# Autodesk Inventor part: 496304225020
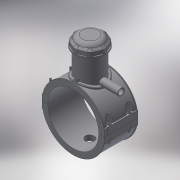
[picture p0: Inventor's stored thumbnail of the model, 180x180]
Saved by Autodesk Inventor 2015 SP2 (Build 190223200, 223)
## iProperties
Created: 2017-07
Part Number: 496304225020
Material: Generic
Description: PLASSON TAPPING SADDLE 225x20
Document SubType Name: Modeling
Designer: KIM
Mass: 1584.4 g
Surface Area: 3366.97 cm^2
Volume: 1584.4 cm^3
Density: 1 g/cm^3
Appearance: Default
Author: KIM
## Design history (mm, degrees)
derived "496304.ipt"
feature "Solid1::496304.ipt"
feature "Solid2::496304.ipt"
feature "Solid4::496304.ipt"
feature "Solid5::496304.ipt"
tag "TaggingFeature1" dims "B_" = 227
body "Solid1"
body "Solid2"
other parameters: "d_" = 225, "L_" = 176, "d_t" = 6, "H_2" = 177, "H_" = 125, "d1" = 256.5, "d148" = 3.375, "d160" = 3.375, "d169" = 3.375, "d192" = 6.3, "d0" = 225, "d2" = 295.1, "d3" = 56.25, "d4" = 176, "d5" = 0, "d6" = 0.1, "d8" = 0, "d19" = 6, "d20" = 6, "d21" = 105.6, "d23" = 0, "d24" = 52.8, "d26" = 0, "d29" = 3, "d30" = 75, "d31" = 6, "d32" = 0, "d33" = 0, "d34" = 0.6, "d40" = 133.38, "d43" = 0, "d45" = 0, "d47" = 233.85, "d70" = 15, "d72" = 0, "d73" = 6, "d75" = 5, "d76" = 0, "d77" = 11.25, "d78" = 142.5, "d79" = 15, "d80" = 70.4, "d82" = 5 deg, "d84" = 4, "d85" = 14, "d86" = 0, "d87" = 3, "d88" = 0, "d89" = 1, "d90" = 1, "d91" = 140.8, "d92" = 0, "d93" = 0.5, "d94" = 118.42105, "d96" = 261.63, "d97" = 3.52, "d98" = 0, "d102" = 2.25, "d120" = 140 deg, "d121" = 24.228, "d122" = 20 deg, "d123" = 513, "d124" = 153.9, "d126" = 0, "d143" = 231.75, "d145" = 24.23077, "d149" = 3.375, "d150" = 26.65385, "d153" = 176, "d154" = 0, "d156" = 128.25, "d157" = 160 deg, "d159" = 6.3, "d161" = 3.375, "d162" = 105.6, "d163" = 0, "d164" = 112.5, "d167" = 22.5, "d168" = 125.12195, "d170" = 3.375, "d172" = 0, "d173" = 1, "d175" = 112.5, "d176" = 20 deg, "d177" = 15.75, "d178" = 31.5, "d180" = 0, "d183" = 12.6, "d184" = 12.6, "d185" = 57.2, "d186" = 57.2, "d187" = 128.25, "d188" = 9.45, "d189" = 15.75, "d190" = 0, "d191" = 192.375, "d193" = 6.3, "d194" = 6.16, "d195" = 90 deg, "d197" = 0, "d199" = 0, "d200" = 15.75, "d202" = 0, "d203" = 177, "d204" = 85.5, "d205" = 63, "d206" = 76.5, "d207" = 132.75, "d208" = 138.06, "d209" = 164.61, "d210" = 77.4, "d212" = 72, "d213" = 36, "d216" = 0, "d217" = 22.5, "d218" = 22.5, "d219" = 4.5, "d222" = 225, "d224" = 0, "d230" = 4.5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
